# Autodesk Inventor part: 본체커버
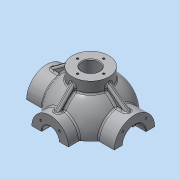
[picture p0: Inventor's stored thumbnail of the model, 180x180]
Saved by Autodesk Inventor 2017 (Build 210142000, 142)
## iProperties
Created: 2015-12
Part Number: 본체커버
Material: 알루미늄 6061
Document SubType Name: Modeling
Designer: mduedu
Density: 2.71 g/cm^3
Mass: 589.734 g
Surface Area: 460.056 cm^2
Volume: 217.614 cm^3
Appearance: 알루미늄 - 평지
Author: mduedu
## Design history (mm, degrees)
sketch "스케치1"
  geometry: L1 (-53, 0)-(53, 0); A1 r 53 centre (0, 0) between (53, 0) and (-53, 0); 2 further points
  constraints: 2 coincident, 2 end point, 2 point on circle, 1 centre point, 1 horizontal, 1 midpoint
  dimensions: "d0" = 53 radius of A1
revolve "회전1" sketch "스케치1" stored, may be unused: angle "d2" = 90 deg
feature "쉘1" dims "d11" = 10
node "작업 평면1"
sketch "스케치2"
  geometry: C1 r 31 at (0, 0); 1 further point
  constraints: 1 centre point, 1 coincident
  dimensions: "d4" = 62 diameter of C1
extrude "돌출1" join sketch "스케치2" stored distance "d5" = 10; taper "d6" = 0 deg
node "작업 평면2"
sketch "스케치3"
  geometry: C1 r 28 at (0, 0); 1 further point
  constraints: 1 centre point, 1 coincident
  dimensions: "d8" = 56 diameter of C1
extrude "돌출2" join sketch "스케치3" stored distance "d9" = 10; taper "d10" = 0 deg
hole "구멍1" diameter "d14" = 35; stored, may be unused: countersink angle "d18" = 90 deg, drill point angle "d20" = 0 deg; dims "d12" = 10, "d13" = 10, "d15" = 6, "d16" = 4, "d17" = 2, "d19" = 16
hole "구멍2" diameter "d23" = 27; stored, may be unused: countersink angle "d27" = 90 deg, drill point angle "d29" = 0 deg; dims "d21" = 10, "d22" = 10, "d24" = 6, "d25" = 4, "d26" = 2, "d28" = 16
fillet "모깎기1" dims "d30" = 0.3
hole "구멍3" diameter "d33" = 26; stored, may be unused: countersink angle "d37" = 90 deg, drill point angle "d39" = 0 deg; dims "d31" = 10, "d32" = 10, "d34" = 6, "d35" = 4, "d36" = 2, "d38" = 16
chamfer "모따기1" distance "d40" = 1; stored, may be unused: second distance "d41" = 2, angle "d42" = 45 deg
sketch "스케치4"
  geometry: L1 (0, 0)-(0, -25); L2 (0, 0)-(-17.678, -17.678); A1 r 25 centre (0, 0) between (-17.678, -17.678) and (0, -25); 1 further point
  constraints: 4 end point, 2 point on circle, 1 centre point, 1 coincident, 1 vertical
  dimensions: "d43" = 50 diameter of A1; "d47" = 45 deg angle of L1 L2
hole "구멍4" sketch "스케치4" at (-17.678, -17.678) diameter "d49" = 3.242; stored, may be unused: countersink angle "d53" = 90 deg, drill point angle "d55" = 118 deg; dims "d50" = 11, "d51" = 4, "d52" = 2, "d54" = 13
sketch "스케치5"
  geometry: L1 (0, 0)-(0, -20); L2 (0, 0)-(-14.142, -14.142); A1 r 20 centre (0, 0) between (0, -20) and (-14.142, -14.142); 2 further points
  constraints: 4 end point, 2 coincident, 2 point on circle, 1 centre point, 1 vertical
  dimensions: "d59" = 40 diameter of A1; "d65" = 45 deg angle of L1 L2
hole "구멍5" sketch "스케치5" at (-14.142, -14.142) diameter "d67" = 3.242; stored, may be unused: countersink angle "d71" = 90 deg, drill point angle "d73" = 118 deg; dims "d68" = 8, "d69" = 4, "d70" = 2, "d72" = 10
node "작업 평면3"
sketch "스케치6"
  geometry: C1 r 65 at (0, 0); 1 further point
  constraints: 1 centre point, 1 coincident
  dimensions: "d78" = 130 diameter of C1
extrude "돌출3" join sketch "스케치6" distance "d80" = 10; taper "d81" = 0 deg
sketch "스케치7"
  geometry: C1 r 20 at (0, 0); 1 further point
  constraints: 1 centre point, 1 coincident
  dimensions: "d82" = 40 diameter of C1
extrude "돌출4" join sketch "스케치7" stored distance "d84" = 10; taper "d85" = 0 deg
sketch "스케치8"
  geometry: 2 further points
  constraints: 1 coincident
hole "구멍6" sketch "스케치8" at (0, 0) diameter "d86" = 20; stored, may be unused: countersink angle "d90" = 90 deg, drill point angle "d92" = 118 deg; dims "d87" = 7, "d88" = 40, "d89" = 5, "d91" = 10
fillet "모깎기2" dims "d93" = 0.3
sketch "스케치9"
  geometry: L1 (65, -75)-(-65, -75) reference; L2 (-45, -75)-(-38.245, -36.692); A1 r 53 centre (0, 0) between (42.988, 31) and (42.988, -31) reference; 1 further point
  constraints: 2 end point, 1 point on circle, 1 point on line
  dimensions: "d94" = 45 horizontal distance of L2.start point (0, 0); "d95" = 80 deg angle of L2 L1
feature "리브1" sketch "스케치9" dims "d96" = 1, "d97" = 8, "d98" = 0, "d99" = 0, "d100" = 1, "d101" = 1
sketch "스케치10"
  geometry: L1 (0, 0)-(0, -55); L2 (0, 0)-(-38.891, -38.891); A1 r 55 centre (0, 0) between (0, -55) and (-38.891, -38.891); 2 further points
  constraints: 4 end point, 2 coincident, 2 point on circle, 1 centre point, 1 vertical
  dimensions: "d105" = 110 diameter of A1; "d107" = 45 deg angle of L1 L2
hole "구멍7" sketch "스케치10" at (-38.891, -38.891) diameter "d109" = 10; stored, may be unused: countersink angle "d113" = 90 deg, drill point angle "d115" = 118 deg; dims "d110" = 7, "d111" = 40, "d112" = 5, "d114" = 10
fillet "모깎기3" dims "d120" = 3
fillet "모깎기4" dims "d121" = 3, "d122" = 3
fillet "모깎기5" dims "d123" = 3
fillet "모깎기6" dims "d124" = 3
sketch "스케치11"
  geometry: C1 r 5 at (-38.891, 38.891) reference; C2 r 5 at (38.891, 38.891) reference; C3 r 5 at (38.891, -38.891) reference; C4 r 5 at (-38.891, -38.891) reference; C5 r 20 at (0, 0) reference; C6 r 65 at (0, 0) reference; 1 further point
  constraints: 3 other
feature "엠보싱1" sketch "스케치11" dims "d125" = 0.5, "d126" = 0
sketch "스케치12"
  geometry: L1 (0, 100)-(0, -100); L2 (0, 100)-(-150, 100); L3 (-150, 100)-(-150, -100); L4 (-150, -100)-(0, -100); 2 further points
  constraints: 8 end point, 3 perpendicular, 1 coincident, 1 midpoint, 1 vertical
  dimensions: "d127" = 200 distance of L2.end L3.end; "d129" = 150 distance of L3.end L1.end
extrude "돌출5" cut sketch "스케치12" stored distance "d130" = 10; taper "d131" = 0 deg
sketch "스케치13"
  geometry: C1 r 7 at (0, -53); A1 r 53 centre (0, 0) between (-42.113, -32.179) and (42.113, -32.179) reference; 1 further point
  constraints: 1 centre point, 1 point on circle
  dimensions: "d132" = 14 diameter of C1
extrude "돌출6" join sketch "스케치13" distance "d133" = 5; taper "d134" = 0 deg
sketch "스케치14"
  geometry: C1 r 7 at (0, 0) reference; 1 further point
extrude "돌출7" cut sketch "스케치14" stored distance "d135" = 5; taper "d136" = 0 deg
sketch "스케치15"
  geometry: C1 r 2.25 at (0, 53); A1 r 7 centre (0, 53) between (6.965, 52.302) and (-6.965, 52.302) reference; 1 further point
  constraints: 1 centre point, 1 coincident
  dimensions: "d139" = 4.5 diameter of C1
extrude "돌출8" cut sketch "스케치15" stored distance "d141" = 5; taper "d142" = 0 deg
fillet "모깎기7" dims "d143" = 3
fillet "모깎기8" dims "d144" = 1
fillet "모깎기9" dims "d145" = 1
fillet "모깎기10" dims "d146" = 1
node "작업 평면4"
sketch "스케치16"
  geometry: C1 r 28 at (0, 0); 1 further point
  constraints: 1 centre point, 1 coincident
  dimensions: "d148" = 56 diameter of C1
extrude "돌출9" join sketch "스케치16" stored distance "d150" = 5; taper "d151" = 0 deg
hole "구멍8" diameter "d154" = 26; stored, may be unused: countersink angle "d158" = 90 deg, drill point angle "d160" = 118 deg; dims "d152" = 10, "d153" = 10, "d155" = 6, "d156" = 4, "d157" = 2, "d159" = 8
sketch "스케치17" dims "d161" = 40
  geometry: 3 further points
  constraints: 2 vertical alignment, 1 coincident, 2 other
hole "구멍9" sketch "스케치17" at (0, 20) diameter "d163" = 3.242; stored, may be unused: countersink angle "d167" = 90 deg, drill point angle "d169" = 118 deg; dims "d164" = 8, "d165" = 4, "d166" = 2, "d168" = 10
fillet "모깎기11" dims "d173" = 3
chamfer "모따기2" distance "d174" = 1; stored, may be unused: second distance "d175" = 2, angle "d176" = 45 deg
sketch "스케치18"
  geometry: L1 (28, 62)-(28, 46.637) reference; L2 (67, 31)-(44.497, 31) reference; L3 (28, 55)-(60, 31); L4 (-28, 62)-(28, 62) reference; L5 (67, 31)-(67, 0) reference; 1 further point
  constraints: 2 end point, 2 point on line
  dimensions: "d177" = 7 distance from line of L3.start L4; "d178" = 7 distance from line of L3.end L5
feature "리브2" sketch "스케치18" dims "d179" = 1, "d180" = 8, "d181" = 0, "d182" = 0, "d183" = 1, "d184" = 1
fillet "모깎기12" dims "d185" = 3
fillet "모깎기13" dims "d186" = 3
sketch "스케치19"
  geometry: L1 (62, 28)-(46.637, 28) reference; L2 (28, 62)-(28, 46.637) reference; L3 (55, 28)-(28, 55); L4 (0, 62)-(28, 62) reference; L5 (62, 28)-(62, -28) reference; 1 further point
  constraints: 2 end point, 2 point on line
  dimensions: "d187" = 7 distance from line of L3.end L4; "d188" = 7 distance from line of L3.start L5
feature "리브3" sketch "스케치19" dims "d189" = 1, "d190" = 8, "d191" = 0, "d192" = 0, "d193" = 1, "d194" = 1
fillet "모깎기14" dims "d195" = 3
fillet "모깎기15" dims "d196" = 3
node "솔리드1"
mirror "대칭1"
mirror "대칭2"
pattern_circular "원형 패턴1" dims angle "d57" = 360 deg
mirror "대칭3"
pattern_circular "원형 패턴2" dims angle "d75" = 360 deg
pattern_circular "원형 패턴3" dims angle "d103" = 360 deg
pattern_circular "원형 패턴4" dims angle "d118" = 360 deg
pattern_circular "원형 패턴5" dims angle "d171" = 360 deg
mirror "대칭4"
node "투영된 루프1"
other parameters: "d3" = 67, "d7" = 62, "d77" = -85, "d147" = 62
